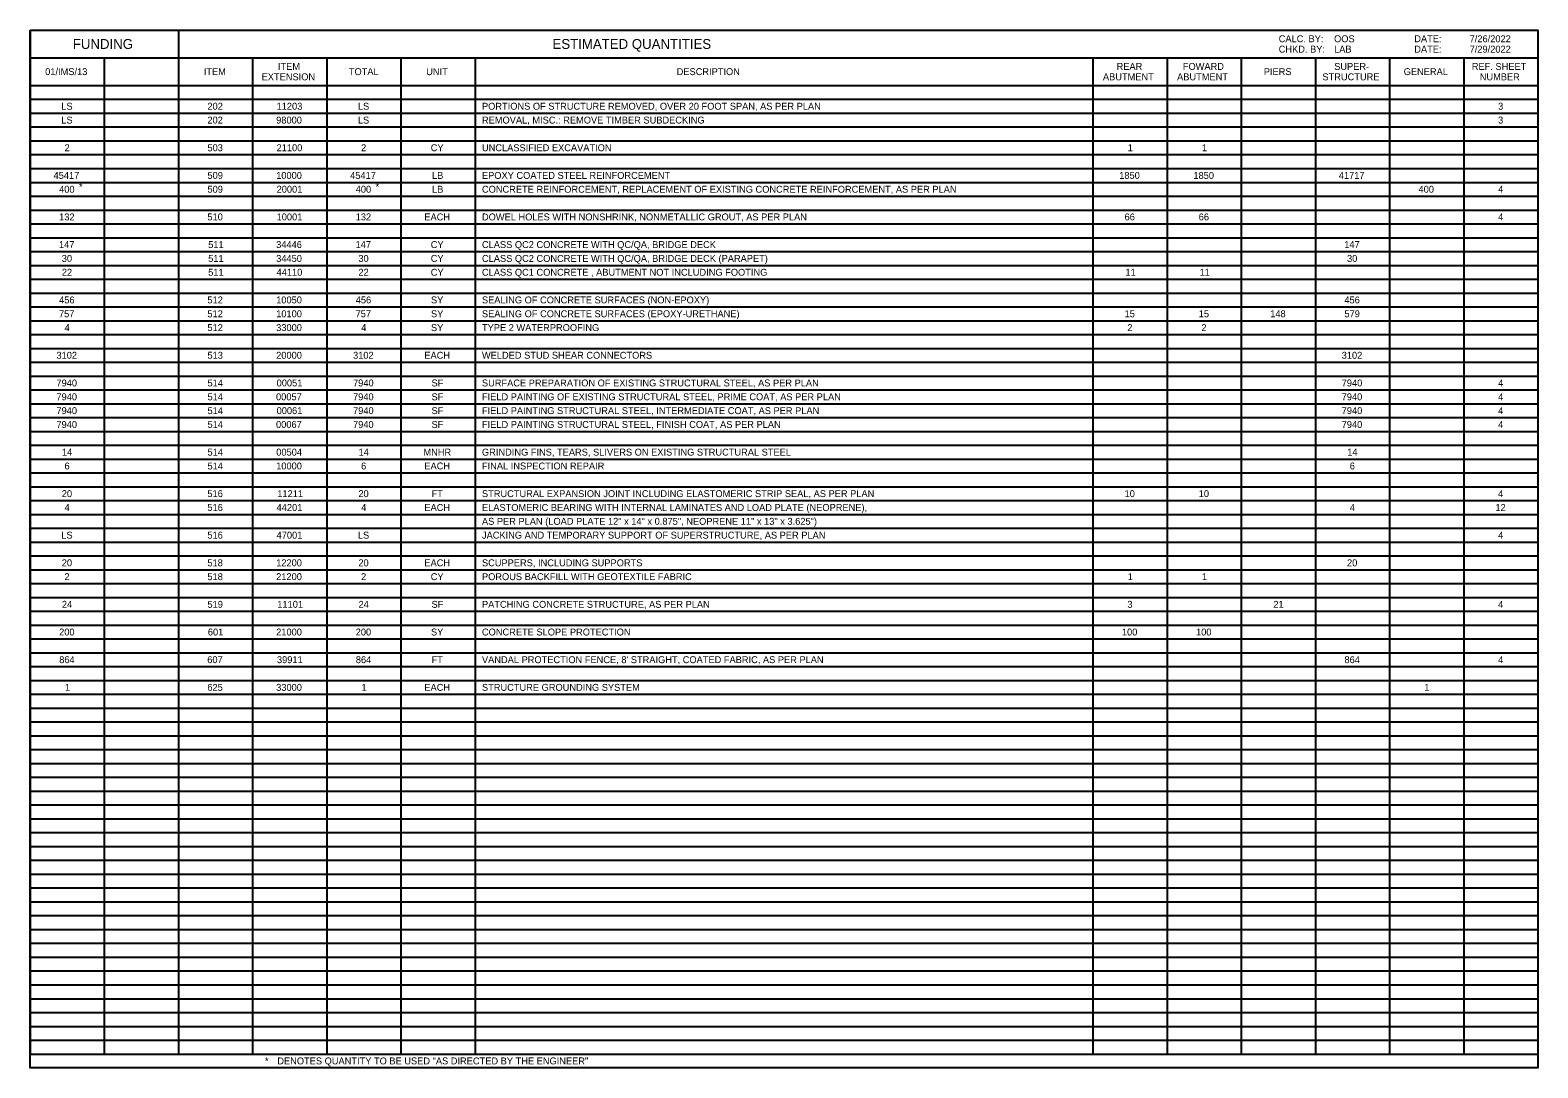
# Model space of a CAD drawing. Extents: x 15570.4 to 15600.9, y 7563.7 to 7584.7.
import ezdxf

# ---------------------------------------------------------------- set-up
doc = ezdxf.new("R2010")
doc.units = 0
for name, color, linetype in [('BR_P_Gen_Text', 7, 'Continuous'), ('SC_Scratch1', 7, 'Continuous'), ('SH_Data', 7, 'Continuous')]:
    doc.layers.add(name, color=color, linetype=linetype)

msp = doc.modelspace()

# ---------------------------------------------------------------- linework, layer by layer
at = {"layer": 'BR_P_Gen_Text'}
for p, q in [((15570.429, 7584.675), (15570.429, 7563.955)), ((15570.429, 7584.675), (15600.929, 7584.675)), ((15573.429, 7584.675), (15573.429, 7563.955)), ((15600.929, 7584.675), (15600.929, 7563.955)), ((15570.429, 7584.115), (15600.929, 7584.115)), ((15571.929, 7584.115), (15571.929, 7563.955)), ((15574.929, 7584.115), (15574.929, 7563.955)), ((15576.429, 7584.115), (15576.429, 7563.955)), ((15577.929, 7584.115), (15577.929, 7563.955)), ((15579.429, 7584.115), (15579.429, 7563.955)), ((15591.929, 7584.115), (15591.929, 7563.955)), ((15593.429, 7584.115), (15593.429, 7563.955)), ((15594.929, 7584.115), (15594.929, 7563.955)), ((15596.429, 7584.115), (15596.429, 7563.955)), ((15597.929, 7584.115), (15597.929, 7563.955)), ((15599.429, 7584.115), (15599.429, 7563.955)), ((15570.429, 7583.555), (15600.929, 7583.555)), ((15570.429, 7583.275), (15600.929, 7583.275)), ((15570.429, 7582.995), (15600.929, 7582.995)), ((15570.429, 7582.715), (15600.929, 7582.715)), ((15570.429, 7582.435), (15600.929, 7582.435)), ((15570.429, 7582.155), (15600.929, 7582.155)), ((15570.429, 7581.875), (15600.929, 7581.875)), ((15570.429, 7581.595), (15600.929, 7581.595)), ((15570.429, 7581.315), (15600.929, 7581.315)), ((15570.429, 7581.035), (15600.929, 7581.035)), ((15570.429, 7580.755), (15600.929, 7580.755)), ((15570.429, 7580.475), (15600.929, 7580.475)), ((15570.429, 7580.195), (15600.929, 7580.195)), ((15570.429, 7579.915), (15600.929, 7579.915)), ((15570.429, 7579.635), (15600.929, 7579.635)), ((15570.429, 7579.355), (15600.929, 7579.355)), ((15570.429, 7579.075), (15600.929, 7579.075)), ((15570.429, 7578.795), (15600.929, 7578.795)), ((15570.429, 7578.515), (15600.929, 7578.515)), ((15570.429, 7578.235), (15600.929, 7578.235)), ((15570.429, 7577.955), (15600.929, 7577.955)), ((15570.429, 7577.675), (15600.929, 7577.675)), ((15570.429, 7577.395), (15600.929, 7577.395)), ((15570.429, 7577.115), (15600.929, 7577.115)), ((15570.429, 7576.835), (15600.929, 7576.835)), ((15570.429, 7576.555), (15600.929, 7576.555)), ((15570.429, 7576.275), (15600.929, 7576.275)), ((15570.429, 7575.995), (15600.929, 7575.995)), ((15570.429, 7575.715), (15600.929, 7575.715)), ((15570.429, 7575.435), (15600.929, 7575.435)), ((15570.429, 7575.155), (15600.929, 7575.155)), ((15570.429, 7574.875), (15600.929, 7574.875)), ((15570.429, 7574.595), (15600.929, 7574.595)), ((15570.429, 7574.315), (15600.929, 7574.315)), ((15570.429, 7574.035), (15600.929, 7574.035)), ((15570.429, 7573.755), (15600.929, 7573.755)), ((15570.429, 7573.475), (15600.929, 7573.475)), ((15570.429, 7573.195), (15600.929, 7573.195)), ((15570.429, 7572.915), (15600.929, 7572.915)), ((15570.429, 7572.635), (15600.929, 7572.635)), ((15570.429, 7572.355), (15600.929, 7572.355)), ((15570.429, 7572.075), (15600.929, 7572.075)), ((15570.429, 7571.795), (15600.929, 7571.795)), ((15570.429, 7571.515), (15600.929, 7571.515)), ((15570.429, 7571.235), (15600.929, 7571.235)), ((15570.429, 7570.955), (15600.929, 7570.955)), ((15570.429, 7570.675), (15600.929, 7570.675)), ((15570.429, 7570.395), (15600.929, 7570.395)), ((15570.429, 7570.115), (15600.929, 7570.115)), ((15570.429, 7569.835), (15600.929, 7569.835)), ((15570.429, 7569.555), (15600.929, 7569.555)), ((15570.429, 7569.275), (15600.929, 7569.275)), ((15570.429, 7568.995), (15600.929, 7568.995)), ((15570.429, 7568.715), (15600.929, 7568.715)), ((15570.429, 7568.435), (15600.929, 7568.435)), ((15570.429, 7568.155), (15600.929, 7568.155)), ((15570.429, 7567.875), (15600.929, 7567.875)), ((15570.429, 7567.595), (15600.929, 7567.595)), ((15570.429, 7567.315), (15600.929, 7567.315)), ((15570.429, 7567.035), (15600.929, 7567.035)), ((15570.429, 7566.755), (15600.929, 7566.755)), ((15570.429, 7566.475), (15600.929, 7566.475)), ((15570.429, 7566.195), (15600.929, 7566.195)), ((15570.429, 7565.915), (15600.929, 7565.915)), ((15570.429, 7565.635), (15600.929, 7565.635)), ((15570.429, 7565.355), (15600.929, 7565.355)), ((15570.429, 7565.075), (15600.929, 7565.075)), ((15570.429, 7564.795), (15600.929, 7564.795)), ((15570.429, 7564.515), (15600.929, 7564.515)), ((15570.429, 7564.235), (15600.929, 7564.235)), ((15570.429, 7563.955), (15600.929, 7563.955))]:
    msp.add_line(p, q, dxfattribs=at)
at = {"layer": 'SC_Scratch1'}
msp.add_lwpolyline([(15570.429, 7584.675), (15600.929, 7584.675), (15600.929, 7563.675), (15570.429, 7563.675)], close=True, dxfattribs=at)
at = {"layer": 'SH_Data'}
msp.add_lwpolyline([(15570.429, 7584.675), (15600.929, 7584.675), (15600.929, 7563.675), (15570.429, 7563.675)], close=True, dxfattribs=at)

# ---------------------------------------------------------------- texts
at = {"layer": 'BR_P_Gen_Text'}
for s, height, p in [('FUNDING', 0.2, (15571.292, 7584.295)), ('ESTIMATED QUANTITIES', 0.2, (15580.996, 7584.295)), ('CALC. BY:', 0.14, (15595.687, 7584.43)), ('OOS', 0.14, (15596.807, 7584.43)), ('DATE:', 0.14, (15598.429, 7584.43)), ('7/26/2022', 0.14, (15599.549, 7584.43)), ('CHKD. BY:', 0.14, (15595.687, 7584.22)), ('LAB', 0.14, (15596.807, 7584.22)), ('DATE:', 0.14, (15598.429, 7584.22)), ('7/29/2022', 0.14, (15599.549, 7584.22)), ('01/IMS/13', 0.14, (15570.733, 7583.765)), ('ITEM', 0.14, (15573.942, 7583.765)), ('ITEM', 0.14, (15575.442, 7583.87)), ('TOTAL', 0.14, (15576.876, 7583.765)), ('UNIT', 0.14, (15578.441, 7583.765)), ('DESCRIPTION', 0.14, (15583.508, 7583.765)), ('REAR', 0.14, (15592.407, 7583.87)), ('FOWARD', 0.14, (15593.747, 7583.87)), ('PIERS', 0.14, (15595.385, 7583.765)), ('SUPER-', 0.14, (15596.809, 7583.87)), ('GENERAL', 0.14, (15598.215, 7583.765)), ('REF. SHEET', 0.14, (15599.593, 7583.87)), ('EXTENSION', 0.14, (15575.111, 7583.66)), ('ABUTMENT', 0.14, (15592.131, 7583.66)), ('ABUTMENT', 0.14, (15593.631, 7583.66)), ('STRUCTURE', 0.14, (15596.571, 7583.66)), ('NUMBER', 0.14, (15599.754, 7583.66)), ('LS', 0.14, (15571.059, 7583.065)), ('LS', 0.14, (15571.059, 7582.785)), ('202', 0.14, (15574.015, 7583.065)), ('202', 0.14, (15574.015, 7582.785)), ('98000', 0.14, (15575.406, 7582.785)), ('11203', 0.14, (15575.414, 7583.065)), ('LS', 0.14, (15577.059, 7583.065)), ('LS', 0.14, (15577.059, 7582.785)), ('PORTIONS OF STRUCTURE REMOVED, OVER 20 FOOT SPAN, AS PER PLAN', 0.14, (15579.569, 7583.065)), ('REMOVAL, MISC.: REMOVE TIMBER SUBDECKING', 0.14, (15579.569, 7582.785)), ('3', 0.14, (15600.125, 7583.065)), ('3', 0.14, (15600.125, 7582.785)), ('2', 0.14, (15571.124, 7582.225)), ('503', 0.14, (15574.016, 7582.225)), ('21100', 0.14, (15575.414, 7582.225)), ('2', 0.14, (15577.124, 7582.225)), ('CY', 0.14, (15578.533, 7582.225)), ('UNCLASSIFIED EXCAVATION', 0.14, (15579.569, 7582.225)), ('1', 0.14, (15592.632, 7582.225)), ('1', 0.14, (15594.132, 7582.225)), ('45417', 0.14, (15570.903, 7581.665)), ('509', 0.14, (15574.016, 7581.665)), ('10000', 0.14, (15575.406, 7581.665)), ('45417', 0.14, (15576.903, 7581.665)), ('LB', 0.14, (15578.559, 7581.665)), ('EPOXY COATED STEEL REINFORCEMENT', 0.14, (15579.569, 7581.665)), ('1850', 0.14, (15592.461, 7581.665)), ('1850', 0.14, (15593.961, 7581.665)), ('41717', 0.14, (15596.903, 7581.665)), ('400', 0.14, (15571.015, 7581.385)), ('*', 0.14, (15571.416, 7581.435)), ('509', 0.14, (15574.016, 7581.385)), ('20001', 0.14, (15575.415, 7581.385)), ('400', 0.14, (15577.015, 7581.385)), ('*', 0.14, (15577.416, 7581.435)), ('LB', 0.14, (15578.559, 7581.385)), ('CONCRETE REINFORCEMENT, REPLACEMENT OF EXISTING CONCRETE REINFORCEMENT, AS PER PLAN', 0.14, (15579.569, 7581.385)), ('400', 0.14, (15598.515, 7581.385)), ('4', 0.14, (15600.126, 7581.385)), ('132', 0.14, (15571.015, 7580.825)), ('510', 0.14, (15574.015, 7580.825)), ('10001', 0.14, (15575.415, 7580.825)), ('132', 0.14, (15577.015, 7580.825)), ('EACH', 0.14, (15578.404, 7580.825)), ('DOWEL HOLES WITH NONSHRINK, NONMETALLIC GROUT, AS PER PLAN', 0.14, (15579.569, 7580.825)), ('66', 0.14, (15592.569, 7580.825)), ('66', 0.14, (15594.069, 7580.825)), ('4', 0.14, (15600.126, 7580.825)), ('147', 0.14, (15571.012, 7580.265)), ('511', 0.14, (15574.031, 7580.265)), ('34446', 0.14, (15575.406, 7580.265)), ('147', 0.14, (15577.012, 7580.265)), ('CY', 0.14, (15578.533, 7580.265)), ('CLASS QC2 CONCRETE WITH QC/QA, BRIDGE DECK', 0.14, (15579.569, 7580.265)), ('147', 0.14, (15597.012, 7580.265)), ('30', 0.14, (15571.069, 7579.985)), ('511', 0.14, (15574.031, 7579.985)), ('34450', 0.14, (15575.406, 7579.985)), ('30', 0.14, (15577.069, 7579.985)), ('CY', 0.14, (15578.533, 7579.985)), ('CLASS QC2 CONCRETE WITH QC/QA, BRIDGE DECK (PARAPET)', 0.14, (15579.569, 7579.985)), ('30', 0.14, (15597.069, 7579.985)), ('22', 0.14, (15571.07, 7579.705)), ('511', 0.14, (15574.031, 7579.705)), ('44110', 0.14, (15575.414, 7579.705)), ('22', 0.14, (15577.07, 7579.705)), ('CY', 0.14, (15578.533, 7579.705)), ('CLASS QC1 CONCRETE , ABUTMENT NOT INCLUDING FOOTING', 0.14, (15579.569, 7579.705)), ('11', 0.14, (15592.585, 7579.705)), ('11', 0.14, (15594.085, 7579.705)), ('456', 0.14, (15571.015, 7579.145)), ('512', 0.14, (15574.015, 7579.145)), ('10050', 0.14, (15575.406, 7579.145)), ('456', 0.14, (15577.015, 7579.145)), ('SY', 0.14, (15578.538, 7579.145)), ('SEALING OF CONCRETE SURFACES (NON-EPOXY)', 0.14, (15579.569, 7579.145)), ('456', 0.14, (15597.015, 7579.145)), ('757', 0.14, (15571.012, 7578.865)), ('512', 0.14, (15574.015, 7578.865)), ('10100', 0.14, (15575.406, 7578.865)), ('757', 0.14, (15577.012, 7578.865)), ('SY', 0.14, (15578.538, 7578.865)), ('SEALING OF CONCRETE SURFACES (EPOXY-URETHANE)', 0.14, (15579.569, 7578.865)), ('15', 0.14, (15592.569, 7578.865)), ('15', 0.14, (15594.069, 7578.865)), ('148', 0.14, (15595.515, 7578.865)), ('579', 0.14, (15597.016, 7578.865)), ('4', 0.14, (15571.126, 7578.585)), ('512', 0.14, (15574.015, 7578.585)), ('33000', 0.14, (15575.406, 7578.585)), ('4', 0.14, (15577.126, 7578.585)), ('SY', 0.14, (15578.538, 7578.585)), ('TYPE 2 WATERPROOFING', 0.14, (15579.569, 7578.585)), ('2', 0.14, (15592.624, 7578.585)), ('2', 0.14, (15594.124, 7578.585)), ('3102', 0.14, (15570.961, 7578.025)), ('513', 0.14, (15574.016, 7578.025)), ('20000', 0.14, (15575.406, 7578.025)), ('3102', 0.14, (15576.961, 7578.025)), ('EACH', 0.14, (15578.404, 7578.025)), ('WELDED STUD SHEAR CONNECTORS', 0.14, (15579.569, 7578.025)), ('3102', 0.14, (15596.961, 7578.025)), ('7940', 0.14, (15570.961, 7577.465)), ('514', 0.14, (15574.017, 7577.465)), ('00051', 0.14, (15575.415, 7577.465)), ('7940', 0.14, (15576.961, 7577.465)), ('SF', 0.14, (15578.549, 7577.465)), ('SURFACE PREPARATION OF EXISTING STRUCTURAL STEEL, AS PER PLAN', 0.14, (15579.569, 7577.465)), ('7940', 0.14, (15596.961, 7577.465)), ('4', 0.14, (15600.126, 7577.465)), ('7940', 0.14, (15570.961, 7577.185)), ('514', 0.14, (15574.017, 7577.185)), ('00057', 0.14, (15575.403, 7577.185)), ('7940', 0.14, (15576.961, 7577.185)), ('SF', 0.14, (15578.549, 7577.185)), ('FIELD PAINTING OF EXISTING STRUCTURAL STEEL, PRIME COAT, AS PER PLAN', 0.14, (15579.569, 7577.185)), ('7940', 0.14, (15596.961, 7577.185)), ('4', 0.14, (15600.126, 7577.185)), ('7940', 0.14, (15570.961, 7576.905)), ('514', 0.14, (15574.017, 7576.905)), ('00061', 0.14, (15575.415, 7576.905)), ('7940', 0.14, (15576.961, 7576.905)), ('SF', 0.14, (15578.549, 7576.905)), ('FIELD PAINTING STRUCTURAL STEEL, INTERMEDIATE COAT, AS PER PLAN', 0.14, (15579.569, 7576.905)), ('7940', 0.14, (15596.961, 7576.905)), ('4', 0.14, (15600.126, 7576.905)), ('7940', 0.14, (15570.961, 7576.625)), ('514', 0.14, (15574.017, 7576.625)), ('00067', 0.14, (15575.403, 7576.625)), ('7940', 0.14, (15576.961, 7576.625)), ('SF', 0.14, (15578.549, 7576.625)), ('FIELD PAINTING STRUCTURAL STEEL, FINISH COAT, AS PER PLAN', 0.14, (15579.569, 7576.625)), ('7940', 0.14, (15596.961, 7576.625)), ('4', 0.14, (15600.126, 7576.625)), ('14', 0.14, (15571.072, 7576.065)), ('514', 0.14, (15574.017, 7576.065)), ('00504', 0.14, (15575.408, 7576.065)), ('14', 0.14, (15577.072, 7576.065)), ('MNHR', 0.14, (15578.385, 7576.065)), ('GRINDING FINS, TEARS, SLIVERS ON EXISTING STRUCTURAL STEEL', 0.14, (15579.569, 7576.065)), ('14', 0.14, (15597.072, 7576.065)), ('6', 0.14, (15571.124, 7575.785)), ('514', 0.14, (15574.017, 7575.785)), ('10000', 0.14, (15575.406, 7575.785)), ('6', 0.14, (15577.124, 7575.785)), ('EACH', 0.14, (15578.404, 7575.785)), ('FINAL INSPECTION REPAIR', 0.14, (15579.569, 7575.785)), ('6', 0.14, (15597.124, 7575.785)), ('20', 0.14, (15571.069, 7575.225)), ('516', 0.14, (15574.015, 7575.225)), ('11211', 0.14, (15575.429, 7575.225)), ('20', 0.14, (15577.069, 7575.225)), ('FT', 0.14, (15578.55, 7575.225)), ('STRUCTURAL EXPANSION JOINT INCLUDING ELASTOMERIC STRIP SEAL, AS PER PLAN', 0.14, (15579.569, 7575.225)), ('10', 0.14, (15592.569, 7575.225)), ('10', 0.14, (15594.069, 7575.225)), ('4', 0.14, (15600.126, 7575.225)), ('4', 0.14, (15571.126, 7574.945)), ('516', 0.14, (15574.015, 7574.945)), ('44201', 0.14, (15575.415, 7574.945)), ('4', 0.14, (15577.126, 7574.945)), ('EACH', 0.14, (15578.404, 7574.945)), ('ELASTOMERIC BEARING WITH INTERNAL LAMINATES AND LOAD PLATE (NEOPRENE),', 0.14, (15579.569, 7574.945)), ('4', 0.14, (15597.126, 7574.945)), ('12', 0.14, (15600.07, 7574.945)), ('AS PER PLAN (LOAD PLATE 12" x 14" x 0.875", NEOPRENE 11" x 13" x 3.625")', 0.14, (15579.569, 7574.665)), ('LS', 0.14, (15571.059, 7574.385)), ('516', 0.14, (15574.015, 7574.385)), ('47001', 0.14, (15575.415, 7574.385)), ('LS', 0.14, (15577.059, 7574.385)), ('JACKING AND TEMPORARY SUPPORT OF SUPERSTRUCTURE, AS PER PLAN', 0.14, (15579.569, 7574.385)), ('4', 0.14, (15600.126, 7574.385)), ('20', 0.14, (15571.069, 7573.825)), ('518', 0.14, (15574.015, 7573.825)), ('12200', 0.14, (15575.406, 7573.825)), ('20', 0.14, (15577.069, 7573.825)), ('EACH', 0.14, (15578.404, 7573.825)), ('SCUPPERS, INCLUDING SUPPORTS', 0.14, (15579.569, 7573.825)), ('20', 0.14, (15597.069, 7573.825)), ('2', 0.14, (15571.124, 7573.545)), ('518', 0.14, (15574.015, 7573.545)), ('21200', 0.14, (15575.406, 7573.545)), ('2', 0.14, (15577.124, 7573.545)), ('CY', 0.14, (15578.533, 7573.545)), ('POROUS BACKFILL WITH GEOTEXTILE FABRIC', 0.14, (15579.569, 7573.545)), ('1', 0.14, (15592.632, 7573.545)), ('1', 0.14, (15594.132, 7573.545)), ('24', 0.14, (15571.072, 7572.985)), ('519', 0.14, (15574.016, 7572.985)), ('11101', 0.14, (15575.429, 7572.985)), ('24', 0.14, (15577.072, 7572.985)), ('SF', 0.14, (15578.549, 7572.985)), ('PATCHING CONCRETE STRUCTURE, AS PER PLAN', 0.14, (15579.569, 7572.985)), ('3', 0.14, (15592.625, 7572.985)), ('21', 0.14, (15595.578, 7572.985)), ('4', 0.14, (15600.126, 7572.985)), ('200', 0.14, (15571.015, 7572.425)), ('601', 0.14, (15574.024, 7572.425)), ('21000', 0.14, (15575.406, 7572.425)), ('200', 0.14, (15577.015, 7572.425)), ('SY', 0.14, (15578.538, 7572.425)), ('CONCRETE SLOPE PROTECTION', 0.14, (15579.569, 7572.425)), ('100', 0.14, (15592.515, 7572.425)), ('100', 0.14, (15594.015, 7572.425)), ('864', 0.14, (15571.017, 7571.865)), ('607', 0.14, (15574.012, 7571.865)), ('39911', 0.14, (15575.422, 7571.865)), ('864', 0.14, (15577.017, 7571.865)), ('FT', 0.14, (15578.55, 7571.865)), ("VANDAL PROTECTION FENCE, 8' STRAIGHT, COATED FABRIC, AS PER PLAN", 0.14, (15579.569, 7571.865)), ('864', 0.14, (15597.017, 7571.865)), ('4', 0.14, (15600.126, 7571.865)), ('1', 0.14, (15571.132, 7571.305)), ('625', 0.14, (15574.014, 7571.305)), ('33000', 0.14, (15575.406, 7571.305)), ('1', 0.14, (15577.132, 7571.305)), ('EACH', 0.14, (15578.404, 7571.305)), ('STRUCTURE GROUNDING SYSTEM', 0.14, (15579.569, 7571.305)), ('1', 0.14, (15598.632, 7571.305)), ('*', 0.14, (15575.179, 7563.745)), ('DENOTES QUANTITY TO BE USED "AS DIRECTED BY THE ENGINEER"', 0.14, (15575.429, 7563.745))]:
    msp.add_text(s, height=height, dxfattribs=at).set_placement(p)

doc.saveas('drawing.dxf')
